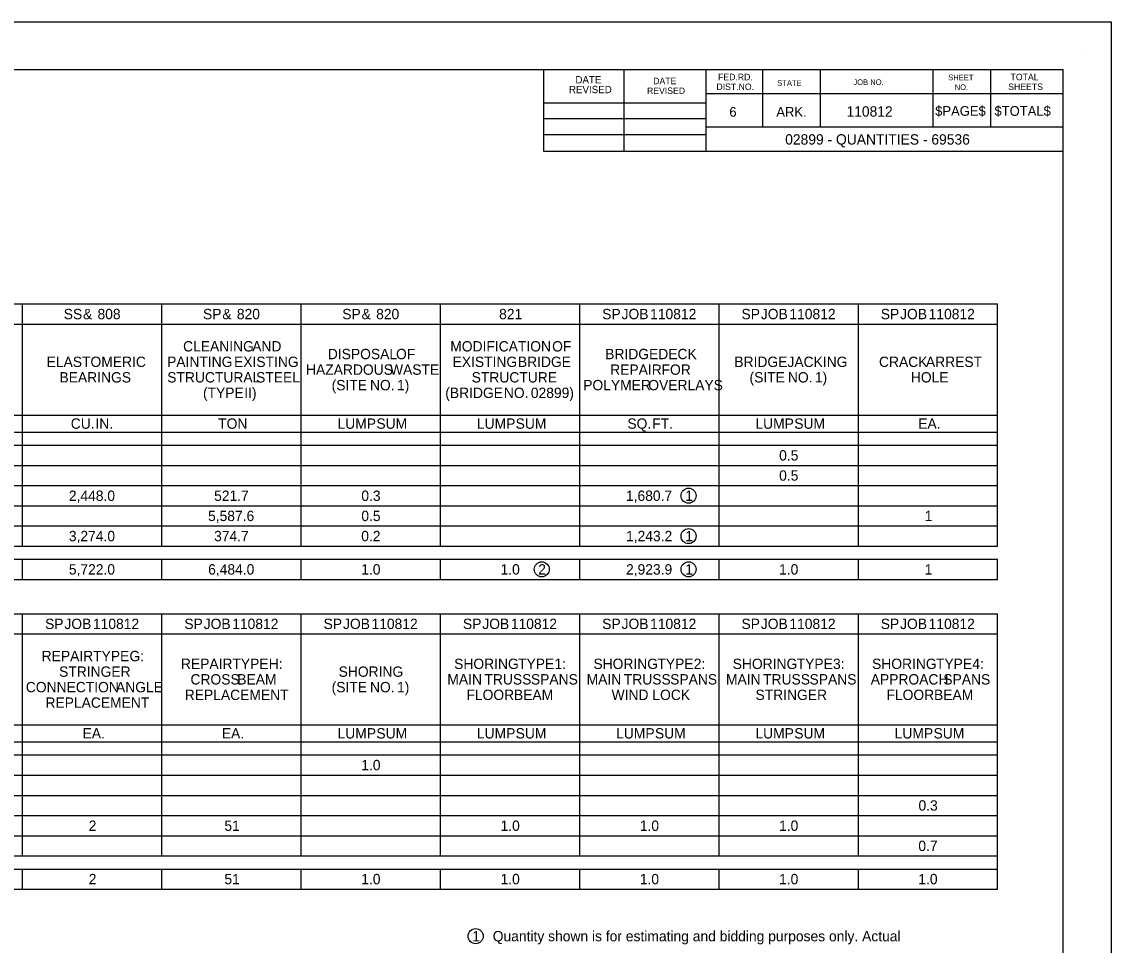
# Model space of a CAD drawing. Extents: x 188 to 14744886, y 129 to 1829278.
# Drawn here: x 208.75 to 221.88, y 139.38 to 150.51 of the extents above; entities that cross this region are included whole.
import ezdxf

# ---------------------------------------------------------------- set-up
doc = ezdxf.new("R2010")
doc.units = 0
for name, color, linetype in [('B_Copy In', 7, 'Continuous'), ('B_Dimensions', 7, 'Continuous'), ('B_Text', 7, 'Continuous'), ('R_Border', 7, 'Continuous'), ('R_No Plot', 7, 'Continuous')]:
    doc.layers.add(name, color=color, linetype=linetype)

msp = doc.modelspace()

# ---------------------------------------------------------------- linework, layer by layer
at = {"layer": 'B_Dimensions'}
for centre in [(216.788, 144.799), (216.788, 144.312), (215.018, 143.911), (216.788, 143.911), (214.221, 139.487)]:
    msp.add_circle(centre, 0.0908, dxfattribs=at)
at = {"layer": 'B_Text'}
for p, q in [((190.192, 147.111), (220.514, 147.111)), ((208.76, 144.19), (208.76, 147.111)), ((210.439, 144.19), (210.439, 147.111)), ((212.118, 144.19), (212.118, 147.111)), ((213.797, 144.19), (213.797, 147.111)), ((215.477, 144.19), (215.477, 147.111)), ((217.156, 144.19), (217.156, 147.111)), ((218.835, 144.19), (218.835, 147.111)), ((220.514, 144.19), (220.514, 147.111)), ((192.357, 146.867), (220.514, 146.867)), ((192.357, 145.772), (220.514, 145.772)), ((190.192, 145.565), (220.514, 145.565)), ((190.192, 145.407), (220.514, 145.407)), ((190.593, 145.164), (220.514, 145.164)), ((190.593, 144.92), (220.514, 144.92)), ((190.593, 144.677), (220.514, 144.677)), ((190.593, 144.434), (220.514, 144.434)), ((190.192, 144.19), (220.514, 144.19)), ((190.192, 144.032), (220.514, 144.032)), ((208.76, 143.789), (208.76, 144.032)), ((210.439, 143.789), (210.439, 144.032)), ((212.118, 143.789), (212.118, 144.032)), ((213.797, 143.789), (213.797, 144.032)), ((215.477, 143.789), (215.477, 144.032)), ((217.156, 143.789), (217.156, 144.032)), ((218.835, 143.789), (218.835, 144.032)), ((220.514, 143.789), (220.514, 144.032)), ((190.192, 143.789), (220.514, 143.789)), ((218.835, 143.789), (220.514, 143.789)), ((190.192, 143.375), (220.514, 143.375)), ((208.76, 140.455), (208.76, 143.375)), ((210.439, 140.455), (210.439, 143.375)), ((212.118, 140.455), (212.118, 143.375)), ((213.797, 140.455), (213.797, 143.375)), ((215.477, 140.455), (215.477, 143.375)), ((217.156, 143.375), (220.514, 143.375)), ((217.156, 140.455), (217.156, 143.375)), ((218.835, 140.455), (218.835, 143.375)), ((220.514, 140.053), (220.514, 143.375)), ((192.357, 143.132), (220.514, 143.132)), ((192.357, 142.037), (220.514, 142.037)), ((190.192, 141.83), (220.514, 141.83)), ((190.192, 141.672), (220.514, 141.672)), ((190.593, 141.428), (220.514, 141.428)), ((190.593, 141.185), (220.514, 141.185)), ((190.593, 140.942), (220.514, 140.942)), ((190.593, 140.698), (220.514, 140.698)), ((198.685, 140.698), (220.514, 140.698)), ((190.192, 140.455), (220.514, 140.455)), ((190.192, 140.297), (220.514, 140.297)), ((208.76, 140.053), (208.76, 140.297)), ((210.439, 140.053), (210.439, 140.297)), ((212.118, 140.053), (212.118, 140.297)), ((213.797, 140.053), (213.797, 140.297)), ((215.477, 140.053), (215.477, 140.297)), ((217.156, 140.053), (217.156, 140.297)), ((218.835, 140.053), (218.835, 140.297)), ((192.357, 140.053), (220.514, 140.053)), ((197.006, 140.053), (218.835, 140.053)), ((218.835, 140.053), (220.514, 140.053))]:
    msp.add_line(p, q, dxfattribs=at)
at = {"layer": 'R_Border'}
for p, q in [((221.525, 150.168), (221.525, 150.168)), ((189.399, 149.937), (221.306, 149.937)), ((215.042, 148.949), (215.042, 149.937)), ((216.01, 148.949), (216.01, 149.937)), ((216.996, 149.937), (216.996, 148.949)), ((217.68, 149.937), (217.68, 149.243)), ((218.374, 149.937), (218.374, 149.243)), ((219.732, 149.937), (219.732, 149.243)), ((220.426, 149.937), (220.426, 149.243)), ((221.306, 129.091), (221.306, 149.937)), ((221.306, 149.643), (216.996, 149.643)), ((221.306, 149.645), (221.306, 149.645)), ((215.042, 149.535), (216.996, 149.535)), ((215.042, 149.349), (216.996, 149.349)), ((221.306, 149.243), (216.996, 149.243)), ((215.042, 149.155), (216.996, 149.155)), ((221.306, 148.949), (215.042, 148.949))]:
    msp.add_line(p, q, dxfattribs=at)
at = {"layer": 'R_No Plot'}
msp.add_lwpolyline([(187.883, 150.514), (221.883, 150.514), (221.883, 128.514), (187.883, 128.514)], close=True, dxfattribs=at)

# ---------------------------------------------------------------- texts
at = {"layer": 'B_Copy In'}
msp.add_text('02899 - QUANTITIES - 69536', height=0.1248, dxfattribs=at).set_placement((217.953, 149.033))
at = {"layer": 'B_Text'}
for s, height, p in [('110812', 0.1248, (218.692, 149.37)), ('SS', 0.1248, (209.255, 146.927)), (' &', 0.1248, (209.441, 146.927)), (' 808', 0.1248, (209.616, 146.927)), ('SP', 0.1248, (210.934, 146.927)), (' &', 0.1248, (211.121, 146.927)), (' 820', 0.1248, (211.296, 146.927)), ('SP', 0.1248, (212.613, 146.927)), (' &', 0.1248, (212.8, 146.927)), (' 820', 0.1248, (212.975, 146.927)), ('821', 0.1248, (214.504, 146.927)), ('SP', 0.1248, (215.747, 146.927)), (' JOB', 0.1248, (215.934, 146.927)), (' 110812', 0.1248, (216.278, 146.927)), ('SP', 0.1248, (217.426, 146.927)), (' JOB', 0.1248, (217.613, 146.927)), (' 110812', 0.1248, (217.957, 146.927)), ('SP', 0.1248, (219.105, 146.927)), (' JOB', 0.1248, (219.292, 146.927)), (' 110812', 0.1248, (219.636, 146.927)), ('CLEANING', 0.1248, (210.694, 146.538)), (' AND', 0.1248, (211.481, 146.538)), ('MODIFICATION', 0.1248, (213.915, 146.538)), (' OF', 0.1248, (215.097, 146.538)), ('ELASTOMERIC', 0.1248, (209.049, 146.351)), ('PAINTING', 0.1248, (210.501, 146.351)), (' EXISTING', 0.1248, (211.262, 146.351)), ('DISPOSAL', 0.1248, (212.439, 146.445)), (' OF', 0.1248, (213.215, 146.445)), ('EXISTING', 0.1248, (213.943, 146.351)), (' BRIDGE', 0.1248, (214.684, 146.351)), ('BRIDGE', 0.1248, (215.783, 146.445)), (' DECK', 0.1248, (216.376, 146.445)), ('BRIDGE', 0.1248, (217.34, 146.351)), (' JACKING', 0.1248, (217.934, 146.351)), ('CRACK', 0.1248, (219.084, 146.351)), (' ARREST', 0.1248, (219.603, 146.351)), ('HAZARDOUS', 0.1248, (212.176, 146.257)), (' WASTE', 0.1248, (213.142, 146.257)), ('REPAIR', 0.1248, (215.843, 146.257)), (' FOR', 0.1248, (216.416, 146.257)), ('BEARINGS', 0.1248, (209.204, 146.164)), ('STRUCTURAL', 0.1248, (210.503, 146.164)), (' STEEL', 0.1248, (211.528, 146.164)), ('(SITE', 0.1248, (212.485, 146.07)), (' NO.', 0.1248, (212.901, 146.07)), (' 1)', 0.1248, (213.227, 146.07)), ('STRUCTURE', 0.1248, (214.173, 146.164)), ('POLYMER', 0.1248, (215.518, 146.07)), (' OVERLAYS', 0.1248, (216.256, 146.07)), ('(SITE', 0.1248, (217.523, 146.164)), (' NO.', 0.1248, (217.939, 146.164)), (' 1)', 0.1248, (218.264, 146.164)), ('HOLE', 0.1248, (219.468, 146.164)), ('(TYPE', 0.1248, (210.934, 145.977)), (' II)', 0.1248, (211.385, 145.977)), ('(BRIDGE', 0.1248, (213.855, 145.977)), (' NO.', 0.1248, (214.515, 145.977)), (' 02899)', 0.1248, (214.84, 145.977)), ('CU.', 0.1248, (209.34, 145.606)), (' IN.', 0.1248, (209.591, 145.606)), ('TON', 0.1248, (211.117, 145.606)), ('LUMP', 0.1248, (212.556, 145.606)), (' SUM', 0.1248, (212.978, 145.606)), ('LUMP', 0.1248, (214.236, 145.606)), (' SUM', 0.1248, (214.657, 145.606)), ('SQ.', 0.1248, (216.05, 145.606)), (' FT.', 0.1248, (216.303, 145.606)), ('LUMP', 0.1248, (217.594, 145.606)), (' SUM', 0.1248, (218.016, 145.606)), ('EA.', 0.1248, (219.557, 145.606)), ('0.5', 0.1248, (217.88, 145.223)), ('0.5', 0.1248, (217.88, 144.98)), ('2,448.0', 0.1248, (209.317, 144.736)), ('521.7', 0.1248, (211.068, 144.736)), ('0.3', 0.1248, (212.843, 144.736)), ('1,680.7', 0.1248, (216.033, 144.736)), ('1', 0.125, (216.748, 144.736)), ('5,587.6', 0.1248, (210.995, 144.493)), ('0.5', 0.1248, (212.843, 144.493)), ('1', 0.125, (219.635, 144.493)), ('3,274.0', 0.1248, (209.317, 144.25)), ('374.7', 0.1248, (211.068, 144.25)), ('0.2', 0.1248, (212.842, 144.25)), ('1,243.2', 0.1248, (216.034, 144.25)), ('1', 0.125, (216.748, 144.25)), ('5,722.0', 0.1248, (209.317, 143.848)), ('6,484.0', 0.1248, (210.996, 143.848)), ('1.0', 0.1248, (212.842, 143.848)), ('1.0', 0.1248, (214.521, 143.848)), ('2', 0.125, (214.975, 143.848)), ('2,923.9', 0.1248, (216.034, 143.848)), ('1', 0.125, (216.748, 143.848)), ('1.0', 0.1248, (217.879, 143.848)), ('1', 0.125, (219.635, 143.848)), ('SP', 0.1248, (209.03, 143.191)), (' JOB', 0.1248, (209.217, 143.191)), (' 110812', 0.1248, (209.561, 143.191)), ('SP', 0.1248, (210.709, 143.191)), (' JOB', 0.1248, (210.896, 143.191)), (' 110812', 0.1248, (211.24, 143.191)), ('SP', 0.1248, (212.388, 143.191)), (' JOB', 0.1248, (212.576, 143.191)), (' 110812', 0.1248, (212.919, 143.191)), ('SP', 0.1248, (214.068, 143.191)), (' JOB', 0.1248, (214.255, 143.191)), (' 110812', 0.1248, (214.599, 143.191)), ('SP', 0.1248, (215.747, 143.191)), (' JOB', 0.1248, (215.934, 143.191)), (' 110812', 0.1248, (216.278, 143.191)), ('SP', 0.1248, (217.426, 143.191)), (' JOB', 0.1248, (217.613, 143.191)), (' 110812', 0.1248, (217.957, 143.191)), ('SP', 0.1248, (219.105, 143.191)), (' JOB', 0.1248, (219.292, 143.191)), (' 110812', 0.1248, (219.636, 143.191)), ('REPAIR', 0.1248, (208.989, 142.803)), (' TYPE', 0.1248, (209.563, 142.803)), (' G:', 0.1248, (210.001, 142.803)), ('REPAIR', 0.1248, (210.668, 142.709)), (' TYPE', 0.1248, (211.242, 142.709)), (' H:', 0.1248, (211.68, 142.709)), ('SHORING', 0.1248, (213.962, 142.709)), (' TYPE', 0.1248, (214.686, 142.709)), (' 1:', 0.1248, (215.125, 142.709)), ('SHORING', 0.1248, (215.641, 142.709)), (' TYPE', 0.1248, (216.366, 142.709)), (' 2:', 0.1248, (216.804, 142.709)), ('SHORING', 0.1248, (217.32, 142.709)), (' TYPE', 0.1248, (218.045, 142.709)), (' 3:', 0.1248, (218.483, 142.709)), ('SHORING', 0.1248, (219, 142.709)), (' TYPE', 0.1248, (219.724, 142.709)), (' 4:', 0.1248, (220.162, 142.709)), ('STRINGER', 0.1248, (209.199, 142.615)), ('CROSS', 0.1248, (210.783, 142.522)), (' BEAM', 0.1248, (211.301, 142.522)), ('SHORING', 0.1248, (212.569, 142.615)), ('MAIN', 0.1248, (213.88, 142.522)), (' TRUSS', 0.1248, (214.281, 142.522)), (' SPANS', 0.1248, (214.841, 142.522)), ('MAIN', 0.1248, (215.559, 142.522)), (' TRUSS', 0.1248, (215.961, 142.522)), (' SPANS', 0.1248, (216.52, 142.522)), ('MAIN', 0.1248, (217.239, 142.522)), (' TRUSS', 0.1248, (217.64, 142.522)), (' SPANS', 0.1248, (218.2, 142.522)), ('APPROACH', 0.1248, (218.984, 142.522)), (' SPANS', 0.1248, (219.813, 142.522)), ('CONNECTION', 0.1248, (208.798, 142.428)), (' ANGLE', 0.1248, (209.839, 142.428)), ('(SITE', 0.1248, (212.485, 142.428)), (' NO.', 0.1248, (212.901, 142.428)), (' 1)', 0.1248, (213.227, 142.428)), ('REPLACEMENT', 0.1248, (210.714, 142.335)), ('FLOOR', 0.1248, (214.11, 142.335)), (' BEAM', 0.1248, (214.637, 142.335)), ('WIND', 0.1248, (215.86, 142.335)), (' LOCK', 0.1248, (216.305, 142.335)), ('STRINGER', 0.1248, (217.595, 142.335)), ('FLOOR', 0.1248, (219.174, 142.335)), (' BEAM', 0.1248, (219.701, 142.335)), ('REPLACEMENT', 0.1248, (209.035, 142.241)), ('EA.', 0.1248, (209.482, 141.871)), ('EA.', 0.1248, (211.161, 141.871)), ('LUMP', 0.1248, (212.556, 141.871)), (' SUM', 0.1248, (212.978, 141.871)), ('LUMP', 0.1248, (214.236, 141.871)), (' SUM', 0.1248, (214.657, 141.871)), ('LUMP', 0.1248, (215.915, 141.871)), (' SUM', 0.1248, (216.336, 141.871)), ('LUMP', 0.1248, (217.594, 141.871)), (' SUM', 0.1248, (218.016, 141.871)), ('LUMP', 0.1248, (219.273, 141.871)), (' SUM', 0.1248, (219.695, 141.871)), ('1.0', 0.1248, (212.842, 141.488)), ('0.3', 0.1248, (219.56, 141.001)), ('2', 0.125, (209.556, 140.757)), ('51', 0.1248, (211.192, 140.757)), ('1.0', 0.1248, (214.521, 140.757)), ('1.0', 0.1248, (216.2, 140.757)), ('1.0', 0.1248, (217.879, 140.757)), ('0.7', 0.1248, (219.558, 140.514)), ('2', 0.125, (209.556, 140.113)), ('51', 0.1248, (211.192, 140.113)), ('1.0', 0.1248, (212.842, 140.113)), ('1.0', 0.1248, (214.521, 140.113)), ('1.0', 0.1248, (216.2, 140.113)), ('1.0', 0.1248, (217.879, 140.113)), ('1.0', 0.1248, (219.558, 140.113)), ('1', 0.125, (214.181, 139.425)), ('Quantity shown is for estimating and bidding purposes only. Actual ', 0.1248, (214.427, 139.425))]:
    msp.add_text(s, height=height, dxfattribs=at).set_placement(p)
at = {"layer": 'R_Border'}
for s, height, p in [('DATE', 0.0879, (215.424, 149.771)), ('FED.RD.', 0.0782, (217.144, 149.809)), ('SHEET', 0.0684, (219.918, 149.809)), ('TOTAL', 0.0782, (220.67, 149.809)), ('REVISED', 0.0879, (215.346, 149.653)), ('DATE', 0.0782, (216.362, 149.761)), ('DIST.NO.', 0.0782, (217.124, 149.691)), ('STATE', 0.0684, (217.856, 149.741)), ('JOB NO.', 0.0684, (218.775, 149.751)), ('NO.', 0.0684, (219.996, 149.691)), ('SHEETS', 0.0782, (220.642, 149.691)), ('REVISED', 0.0782, (216.287, 149.643)), ('6', 0.117, (217.28, 149.369)), ('ARK.', 0.1172, (217.846, 149.369)), ('$PAGE$', 0.1172, (219.761, 149.38)), ('$TOTAL$', 0.1172, (220.476, 149.38))]:
    msp.add_text(s, height=height, dxfattribs=at).set_placement(p)

doc.saveas('drawing.dxf')
